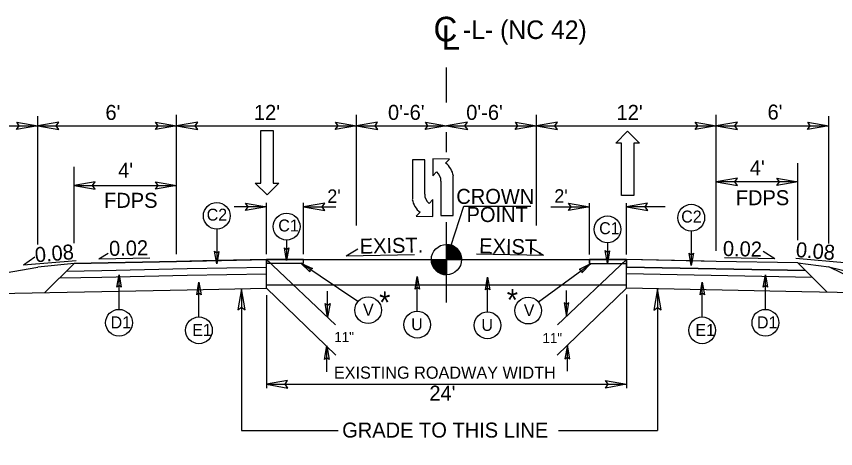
# Model space of a CAD drawing. Extents: x 2111095 to 2115970, y 670428 to 672393.
# Drawn here: x 2112453 to 2112895.7, y 671679.3 to 671912.5 of the extents above; entities that cross this region are included whole.
import ezdxf

# ---------------------------------------------------------------- set-up
doc = ezdxf.new("R2010")
doc.units = 0
for name, color, linetype in [('Old_Level_1', 7, 'Continuous'), ('Old_Level_11', 7, 'Continuous'), ('Old_Level_20', 7, 'Continuous'), ('Old_Level_3', 7, 'Continuous'), ('Prop Lane Arrow CELL', 7, 'Continuous'), ('Prop Leader Line Medium', 7, 'Continuous'), ('Prop Shade Medium', 7, 'Continuous'), ('Typical Grade Point Symbol CELL', 7, 'Continuous'), ('Typical Hinge Slope Arterial CELL', 7, 'Continuous'), ('Typical Pavement Slope CELL', 7, 'Continuous'), ('Typical Pavement Slope Information CELL', 7, 'Continuous'), ('Typical Shoulder Slope CELL', 7, 'Continuous'), ('Typical Shoulder Slope Information CELL', 7, 'Continuous'), ('Typical Terminator CELL', 7, 'Continuous'), ('Typical Text Centerline CELL', 7, 'Continuous'), ('Typical Text General CELL', 7, 'Continuous'), ('Typical Text Grade Point CELL', 7, 'Continuous')]:
    doc.layers.add(name, color=color, linetype=linetype)

msp = doc.modelspace()

# ---------------------------------------------------------------- linework, layer by layer
at = {"layer": 'Old_Level_1'}
for p, q in [((2112588.21, 671781.28), (2112685.41, 671781.28)), ((2112685.41, 671781.28), (2112782.74, 671781.28)), ((2112831.18, 671780.32), (2112782.74, 671781.28)), ((2112588.21, 671765.83), (2112588.21, 671779.34)), ((2112588.21, 671779.34), (2112608.21, 671779.34)), ((2112782.74, 671765.83), (2112782.74, 671779.13)), ((2112891.98, 671777.43), (2113100.62, 671725.29)), ((2113088.33, 671679.28), (2112891.98, 671777.43)), ((2112588.21, 671767.7), (2112685.41, 671767.7)), ((2112685.41, 671767.7), (2112782.58, 671767.7))]:
    msp.add_line(p, q, dxfattribs=at)
at = {"layer": 'Old_Level_11'}
for p, q in [((2112561.29, 671797.66), (2112561.29, 671779.01)), ((2112817.67, 671796.65), (2112817.67, 671777.99)), ((2112599.05, 671791.83), (2112599.05, 671780.85)), ((2112772.42, 671790.37), (2112772.42, 671779.38)), ((2112588.21, 671781.28), (2112625.48, 671745.98)), ((2112782.74, 671781.28), (2112745.47, 671745.98)), ((2112637.57, 671758.66), (2112606.71, 671779.25)), ((2112735.07, 671758.44), (2112763.2, 671778.98)), ((2112508.49, 671754.39), (2112508.49, 671773.08)), ((2112669.61, 671753.38), (2112669.61, 671772.07)), ((2112857.71, 671754.39), (2112857.71, 671773.08)), ((2112551.68, 671750.31), (2112551.68, 671769)), ((2112707.56, 671753), (2112707.56, 671771.69)), ((2112823.57, 671750.31), (2112823.57, 671769)), ((2112588.21, 671765.83), (2112625.7, 671729.73)), ((2112621.2, 671750.11), (2112621.2, 671764.16)), ((2112782.74, 671765.83), (2112745.26, 671729.73)), ((2112750.21, 671750.49), (2112750.21, 671764.54)), ((2112620.71, 671720.7), (2112620.71, 671734.75)), ((2112750.71, 671721.08), (2112750.71, 671735.13))]:
    msp.add_line(p, q, dxfattribs=at)
for points in [[(2112562.44, 671785.69), (2112561.29, 671779.01), (2112560.1, 671785.73), (2112561.29, 671784.88)], [(2112600.2, 671787.53), (2112599.05, 671780.85), (2112597.86, 671787.57), (2112599.05, 671786.72)], [(2112773.57, 671786.07), (2112772.42, 671779.38), (2112771.23, 671786.11), (2112772.42, 671785.25)], [(2112818.82, 671784.68), (2112817.67, 671777.99), (2112816.49, 671784.71), (2112817.67, 671783.86)], [(2112611.63, 671774.58), (2112606.71, 671779.25), (2112612.96, 671776.51), (2112611.59, 671775.99)], [(2112758.48, 671774.11), (2112763.2, 671778.98), (2112757.07, 671775.98), (2112758.46, 671775.52)], [(2112507.34, 671766.39), (2112508.49, 671773.08), (2112509.68, 671766.35), (2112508.49, 671767.21)], [(2112668.46, 671765.38), (2112669.61, 671772.07), (2112670.8, 671765.34), (2112669.61, 671766.2)], [(2112856.56, 671766.39), (2112857.71, 671773.08), (2112858.9, 671766.35), (2112857.71, 671767.21)], [(2112550.52, 671762.31), (2112551.68, 671769), (2112552.86, 671762.28), (2112551.68, 671763.13)], [(2112706.41, 671765.01), (2112707.56, 671771.69), (2112708.75, 671764.97), (2112707.56, 671765.83)], [(2112822.42, 671762.31), (2112823.57, 671769), (2112824.76, 671762.28), (2112823.57, 671763.13)], [(2112622.48, 671757.53), (2112621.2, 671750.11), (2112619.88, 671757.58), (2112621.2, 671756.63)], [(2112748.94, 671757.92), (2112750.21, 671750.49), (2112751.54, 671757.96), (2112750.21, 671757.01)], [(2112619.43, 671727.32), (2112620.71, 671734.75), (2112622.03, 671727.28), (2112620.71, 671728.23)], [(2112751.98, 671727.7), (2112750.71, 671735.13), (2112749.39, 671727.66), (2112750.71, 671728.61)]]:
    msp.add_lwpolyline(points, close=True, dxfattribs=at)
for centre in [(2112561.29, 671804.88), (2112817.67, 671803.86), (2112599.05, 671799.05), (2112772.42, 671797.58), (2112643.06, 671753.98), (2112729.58, 671753.75), (2112508.49, 671747.17), (2112857.71, 671747.17), (2112551.68, 671743.09), (2112669.61, 671746.16), (2112707.56, 671745.79), (2112823.57, 671743.09)]:
    msp.add_circle(centre, 7.22, dxfattribs=at)
at = {"layer": 'Old_Level_3'}
for p, q in [((2112574.64, 671688.99), (2112626.87, 671688.99)), ((2112745.97, 671688.99), (2112799.41, 671688.99))]:
    msp.add_line(p, q, dxfattribs=at)
at = {"layer": 'Prop Lane Arrow CELL'}
for p, q in [((2112585.15, 671822.53), (2112585.15, 671850.88)), ((2112585.15, 671850.88), (2112591.83, 671850.88)), ((2112591.83, 671850.88), (2112591.83, 671822.53)), ((2112776.94, 671844.11), (2112783.22, 671850.48)), ((2112783.22, 671850.48), (2112789.7, 671844.11)), ((2112779.98, 671844.11), (2112776.94, 671844.11)), ((2112779.98, 671815.76), (2112779.98, 671844.11)), ((2112789.7, 671844.11), (2112786.66, 671844.11)), ((2112786.66, 671844.11), (2112786.66, 671815.76)), ((2112666.98, 671835.14), (2112666.98, 671813.78)), ((2112673.67, 671835.14), (2112666.98, 671835.14)), ((2112673.67, 671816.62), (2112673.67, 671835.14)), ((2112678.06, 671835.58), (2112677.96, 671826.46)), ((2112686.97, 671835.47), (2112678.06, 671835.58)), ((2112684.85, 671833.35), (2112686.97, 671835.47)), ((2112677.96, 671826.46), (2112680.09, 671828.59)), ((2112689.1, 671805), (2112689.1, 671826.36)), ((2112588.59, 671816.15), (2112582.11, 671822.53)), ((2112582.11, 671822.53), (2112585.15, 671822.53)), ((2112594.87, 671822.53), (2112588.59, 671816.15)), ((2112591.83, 671822.53), (2112594.87, 671822.53)), ((2112682.42, 671823.53), (2112682.42, 671805)), ((2112678.12, 671813.68), (2112676, 671811.55)), ((2112678.02, 671804.57), (2112678.12, 671813.68)), ((2112786.66, 671815.76), (2112779.98, 671815.76)), ((2112671.24, 671806.79), (2112669.11, 671804.67)), ((2112669.11, 671804.67), (2112678.02, 671804.57)), ((2112682.42, 671805), (2112689.1, 671805))]:
    msp.add_line(p, q, dxfattribs=at)
for centre, radius, start, end in [((2112678.62, 671824.76), 10.64, 8.6761, 53.9878), ((2112675.82, 671823.55), 6.63, 360, 49.6582), ((2112680.26, 671816.59), 6.63, 180, 229.6582), ((2112677.47, 671815.38), 10.64, 188.6761, 233.9878)]:
    msp.add_arc(centre, radius, start, end, dxfattribs=at)
at = {"layer": 'Prop Leader Line Medium'}
for p, q in [((2112685.41, 671865.97), (2112685.41, 671884.94)), ((2112464.58, 671789.41), (2112464.58, 671858.67)), ((2112539.61, 671784.23), (2112539.61, 671859.32)), ((2112636.81, 671799.7), (2112636.81, 671859.32)), ((2112734.01, 671799.7), (2112734.01, 671859.32)), ((2112831.18, 671786.02), (2112831.18, 671859.32)), ((2112891.98, 671789.98), (2112891.98, 671858.68)), ((2112377.61, 671853.48), (2112464.58, 671853.48)), ((2112464.58, 671853.48), (2112539.61, 671853.48)), ((2112539.61, 671853.48), (2112636.81, 671853.48)), ((2112636.81, 671853.48), (2112734.01, 671853.48)), ((2112734.01, 671853.48), (2112831.21, 671853.48)), ((2112831.21, 671853.48), (2112891.98, 671853.48)), ((2112685.41, 671839.26), (2112685.41, 671850)), ((2112484.23, 671790.14), (2112484.23, 671831.32)), ((2112875.32, 671791.75), (2112875.32, 671833.27)), ((2112484.23, 671821.28), (2112539.61, 671821.28)), ((2112875.32, 671823.22), (2112831.18, 671823.22)), ((2112588.21, 671784.23), (2112588.21, 671811.82)), ((2112608.21, 671784.23), (2112608.21, 671811.82)), ((2112762.7, 671784.03), (2112762.7, 671811.75)), ((2112782.7, 671784.03), (2112782.7, 671811.75)), ((2112588.21, 671809.79), (2112570.65, 671809.79)), ((2112608.21, 671809.79), (2112625.66, 671809.79)), ((2112741.85, 671809.79), (2112762.7, 671809.79)), ((2112803.64, 671809.79), (2112782.7, 671809.79)), ((2112685.41, 671758.19), (2112685.41, 671801.4)), ((2112574.64, 671765.55), (2112574.64, 671688.99)), ((2112799.41, 671765.49), (2112799.41, 671688.99)), ((2112588.21, 671762.01), (2112588.21, 671711.93)), ((2112782.74, 671762.42), (2112782.74, 671711.93)), ((2112588.21, 671713.98), (2112782.74, 671713.98))]:
    msp.add_line(p, q, dxfattribs=at)
at = {"layer": 'Prop Shade Medium'}
for p, q in [((2112560.98, 671780.73), (2112539.61, 671780.31)), ((2112561.29, 671779.01), (2112560.98, 671780.73)), ((2112561.59, 671780.75), (2112561.29, 671779.01)), ((2112588.21, 671781.28), (2112561.59, 671780.75)), ((2112588.21, 671777.23), (2112588.21, 671781.28)), ((2112588.21, 671781.28), (2112588.21, 671781.28)), ((2112588.22, 671781.28), (2112588.21, 671781.28)), ((2112588.21, 671781.28), (2112588.21, 671779.34)), ((2112608.21, 671781.28), (2112588.22, 671781.28)), ((2112588.22, 671781.28), (2112590.26, 671779.34)), ((2112590.26, 671779.34), (2112588.22, 671781.28)), ((2112608.21, 671779.34), (2112608.21, 671781.28)), ((2112772.09, 671781.28), (2112762.7, 671781.28)), ((2112762.7, 671781.28), (2112762.7, 671779.13)), ((2112772.42, 671779.38), (2112772.09, 671781.28)), ((2112772.75, 671781.28), (2112772.42, 671779.38)), ((2112782.74, 671781.28), (2112772.75, 671781.28)), ((2112780.48, 671779.13), (2112782.74, 671781.28)), ((2112782.74, 671781.28), (2112780.48, 671779.13)), ((2112817.21, 671780.59), (2112782.74, 671781.28)), ((2112782.74, 671781.28), (2112782.74, 671777.23)), ((2112782.74, 671779.13), (2112782.74, 671781.28)), ((2112817.67, 671777.99), (2112817.21, 671780.59)), ((2112484.23, 671779.2), (2112480.09, 671775.06)), ((2112539.61, 671780.31), (2112484.23, 671779.2)), ((2112499.18, 671775.45), (2112545.27, 671776.37)), ((2112545.27, 671776.37), (2112588.21, 671777.23)), ((2112588.21, 671779.34), (2112590.26, 671779.34)), ((2112590.26, 671779.34), (2112608.21, 671779.34)), ((2112762.7, 671779.13), (2112780.48, 671779.13)), ((2112780.48, 671779.13), (2112782.74, 671779.13)), ((2112782.74, 671777.23), (2112879.45, 671775.31)), ((2112818.12, 671780.58), (2112817.67, 671777.99)), ((2112831.18, 671780.32), (2112818.12, 671780.58)), ((2112875.32, 671779.43), (2112831.18, 671780.32)), ((2112879.45, 671775.31), (2112875.32, 671779.43)), ((2112480.09, 671775.06), (2112499.18, 671775.45))]:
    msp.add_line(p, q, dxfattribs=at)
msp.add_lwpolyline([(2112588.21, 671781.28), (2112588.21, 671781.28)], dxfattribs=at)
at = {"layer": 'Typical Grade Point Symbol CELL'}
for p, q in [((2112685.41, 671781.28), (2112685.41, 671789.43)), ((2112677.25, 671781.28), (2112685.41, 671781.28)), ((2112685.39, 671773.12), (2112685.41, 671781.28)), ((2112685.41, 671781.28), (2112685.39, 671773.12)), ((2112693.57, 671781.28), (2112685.41, 671781.28))]:
    msp.add_line(p, q, dxfattribs=at)
for points in [[(2112685.48, 671789.43), (2112685.48, 671789.43), (2112685.48, 671781.28)], [(2112685.65, 671789.43), (2112685.65, 671781.28)], [(2112685.81, 671789.42), (2112685.81, 671781.28)], [(2112685.97, 671789.42), (2112685.97, 671781.28)], [(2112686.14, 671789.4), (2112686.14, 671781.28)], [(2112686.3, 671789.38), (2112686.3, 671781.28)], [(2112686.46, 671789.36), (2112686.46, 671781.28)], [(2112686.63, 671789.34), (2112686.63, 671781.28)], [(2112686.79, 671789.33), (2112686.79, 671781.28)], [(2112686.95, 671789.29), (2112686.95, 671781.28)], [(2112687.12, 671789.25), (2112687.12, 671781.28)], [(2112687.28, 671789.22), (2112687.28, 671781.28)], [(2112687.44, 671789.18), (2112687.44, 671781.28)], [(2112687.6, 671789.13), (2112687.6, 671781.28)], [(2112687.77, 671789.09), (2112687.77, 671781.28)], [(2112687.93, 671789.04), (2112687.93, 671781.28)], [(2112688.09, 671788.98), (2112688.09, 671781.28)], [(2112688.26, 671788.93), (2112688.26, 671781.28)], [(2112688.42, 671788.85), (2112688.42, 671781.28)], [(2112688.58, 671788.78), (2112688.58, 671781.28)], [(2112688.75, 671788.71), (2112688.75, 671781.28)], [(2112688.91, 671788.64), (2112688.91, 671781.28)], [(2112689.07, 671788.56), (2112689.07, 671781.28)], [(2112689.24, 671788.47), (2112689.24, 671781.28)], [(2112689.4, 671788.38), (2112689.4, 671781.28)], [(2112689.56, 671788.29), (2112689.56, 671781.28)], [(2112689.73, 671788.2), (2112689.73, 671781.28)], [(2112689.89, 671788.09), (2112689.89, 671781.28)], [(2112690.05, 671787.98), (2112690.05, 671781.28)], [(2112690.22, 671787.86), (2112690.22, 671781.28)], [(2112690.38, 671787.75), (2112690.38, 671781.28)], [(2112690.54, 671787.62), (2112690.54, 671781.28)], [(2112690.71, 671787.48), (2112690.71, 671781.28)], [(2112690.87, 671787.33), (2112690.87, 671781.28)], [(2112691.03, 671787.19), (2112691.03, 671781.28)], [(2112691.19, 671787.02), (2112691.19, 671781.28)], [(2112691.36, 671786.86), (2112691.36, 671781.28)], [(2112691.52, 671786.68), (2112691.52, 671781.28)], [(2112691.68, 671786.48), (2112691.68, 671781.28)], [(2112691.85, 671786.28), (2112691.85, 671781.28)], [(2112692.01, 671786.06), (2112692.01, 671781.28)], [(2112692.17, 671785.83), (2112692.17, 671781.28)], [(2112692.34, 671785.57), (2112692.34, 671781.28)], [(2112692.5, 671785.3), (2112692.5, 671781.28)], [(2112692.66, 671785.01), (2112692.66, 671781.28)], [(2112677.29, 671781.28), (2112677.29, 671780.39)], [(2112677.45, 671781.28), (2112677.45, 671779.43)], [(2112677.62, 671781.28), (2112677.62, 671778.85)], [(2112677.78, 671781.28), (2112677.78, 671778.36)], [(2112677.94, 671781.28), (2112677.94, 671777.98)], [(2112678.11, 671781.28), (2112678.11, 671777.63)], [(2112678.27, 671781.28), (2112678.27, 671777.33)], [(2112678.43, 671781.28), (2112678.43, 671777.04)], [(2112678.6, 671781.28), (2112678.6, 671776.78)], [(2112678.76, 671781.28), (2112678.76, 671776.55)], [(2112678.92, 671781.28), (2112678.92, 671776.33)], [(2112679.08, 671781.28), (2112679.08, 671776.13)], [(2112679.25, 671781.28), (2112679.25, 671775.93)], [(2112679.41, 671781.28), (2112679.41, 671775.75)], [(2112679.57, 671781.28), (2112679.57, 671775.57)], [(2112679.74, 671781.28), (2112679.74, 671775.4)], [(2112679.9, 671781.28), (2112679.9, 671775.26)], [(2112680.06, 671781.28), (2112680.06, 671775.11)], [(2112680.23, 671781.28), (2112680.23, 671774.97)], [(2112680.39, 671781.28), (2112680.39, 671774.84)], [(2112680.55, 671781.28), (2112680.55, 671774.71)], [(2112680.72, 671781.28), (2112680.72, 671774.61)], [(2112680.88, 671781.28), (2112680.88, 671774.5)], [(2112681.04, 671781.28), (2112681.04, 671774.39)], [(2112681.21, 671781.28), (2112681.21, 671774.28)], [(2112681.37, 671781.28), (2112681.37, 671774.19)], [(2112681.53, 671781.28), (2112681.53, 671774.1)], [(2112681.7, 671781.28), (2112681.7, 671774.01)], [(2112681.86, 671781.28), (2112681.86, 671773.94)], [(2112682.02, 671781.28), (2112682.02, 671773.86)], [(2112682.19, 671781.28), (2112682.19, 671773.79)], [(2112682.35, 671781.28), (2112682.35, 671773.72)], [(2112682.51, 671781.28), (2112682.51, 671773.65)], [(2112682.67, 671781.28), (2112682.67, 671773.59)], [(2112682.84, 671781.28), (2112682.84, 671773.54)], [(2112683, 671781.28), (2112683, 671773.48)], [(2112683.16, 671781.28), (2112683.16, 671773.45)], [(2112683.33, 671781.28), (2112683.33, 671773.39)], [(2112683.49, 671781.28), (2112683.49, 671773.36)], [(2112683.65, 671781.28), (2112683.65, 671773.32)], [(2112683.82, 671781.28), (2112683.82, 671773.28)], [(2112683.98, 671781.28), (2112683.98, 671773.25)], [(2112684.14, 671781.28), (2112684.14, 671773.23)], [(2112684.31, 671781.28), (2112684.31, 671773.19)], [(2112684.47, 671781.28), (2112684.47, 671773.17)], [(2112684.63, 671781.28), (2112684.63, 671773.16)], [(2112684.8, 671781.28), (2112684.8, 671773.14)], [(2112684.96, 671781.28), (2112684.96, 671773.14)], [(2112685.12, 671781.28), (2112685.12, 671773.12)], [(2112685.29, 671781.28), (2112685.29, 671773.12), (2112685.29, 671773.12)], [(2112692.83, 671784.67), (2112692.83, 671781.28)], [(2112692.99, 671784.29), (2112692.99, 671781.28)], [(2112693.15, 671783.83), (2112693.15, 671781.28)], [(2112693.32, 671783.27), (2112693.32, 671781.28)], [(2112693.48, 671782.44), (2112693.48, 671781.28)]]:
    msp.add_lwpolyline(points, dxfattribs=at)
msp.add_circle((2112685.4, 671781.28), 8.16, dxfattribs=at)
for start, end in [(359.9905, 89.9905), (179.9905, 269.9905)]:
    msp.add_arc((2112685.4, 671781.28), 8.16, start, end, dxfattribs=at)
at = {"layer": 'Typical Hinge Slope Arterial CELL'}
msp.add_line((2112377.61, 671761.61), (2112464.58, 671777.25), dxfattribs=at)
at = {"layer": 'Typical Pavement Slope CELL'}
for p, q in [((2112539.61, 671780.31), (2112588.21, 671781.28)), ((2112608.21, 671779.34), (2112608.21, 671781.28)), ((2112762.7, 671779.13), (2112762.7, 671781.28)), ((2112484.23, 671779.2), (2112468.46, 671763.43)), ((2112484.23, 671779.2), (2112539.61, 671780.31)), ((2112499.18, 671775.45), (2112545.27, 671776.37)), ((2112545.27, 671776.37), (2112588.21, 671777.23)), ((2112762.7, 671779.13), (2112782.74, 671779.13)), ((2112879.45, 671775.31), (2112782.74, 671777.23)), ((2112875.32, 671779.43), (2112831.18, 671780.32)), ((2112891.1, 671763.66), (2112875.32, 671779.43)), ((2112476.43, 671771.4), (2112499.18, 671771.86)), ((2112480.09, 671775.06), (2112499.18, 671775.45)), ((2112499.18, 671771.86), (2112545.27, 671772.78)), ((2112545.27, 671772.78), (2112588.21, 671773.64)), ((2112883.12, 671771.64), (2112782.74, 671773.64)), ((2112377.61, 671761.61), (2112499.18, 671764.04)), ((2112499.18, 671764.04), (2112545.27, 671764.97)), ((2112545.27, 671764.97), (2112588.21, 671765.83)), ((2112877.47, 671763.93), (2112782.74, 671765.83)), ((2112951.96, 671762.44), (2112877.47, 671763.93))]:
    msp.add_line(p, q, dxfattribs=at)
at = {"layer": 'Typical Pavement Slope Information CELL'}
for p, q in [((2112631.2, 671783.26), (2112637.54, 671787.09)), ((2112737.78, 671783.4), (2112731.44, 671787.23)), ((2112862.79, 671781.7), (2112856.45, 671785.54)), ((2112456.96, 671778.44), (2112463.04, 671782.67)), ((2112456.96, 671778.44), (2112485.38, 671780.83)), ((2112497.64, 671781.74), (2112502.62, 671784.75)), ((2112497.64, 671781.74), (2112525.1, 671782.29)), ((2112631.2, 671783.26), (2112668.08, 671784)), ((2112737.78, 671783.4), (2112701.71, 671784.12)), ((2112862.79, 671781.7), (2112835.66, 671782.24)), ((2112902.52, 671779.39), (2112874.1, 671781.78))]:
    msp.add_line(p, q, dxfattribs=at)
at = {"layer": 'Typical Shoulder Slope CELL'}
for p, q in [((2112484.23, 671779.2), (2112464.58, 671777.25)), ((2112875.32, 671779.43), (2112891.98, 671777.43))]:
    msp.add_line(p, q, dxfattribs=at)
at = {"layer": 'Typical Terminator CELL'}
for points in [[(2112453.19, 671855.44), (2112464.58, 671853.48), (2112453.13, 671851.45), (2112454.59, 671853.48)], [(2112475.97, 671855.44), (2112464.58, 671853.48), (2112476.04, 671851.45), (2112474.58, 671853.48)], [(2112528.22, 671855.44), (2112539.61, 671853.48), (2112528.16, 671851.45), (2112529.62, 671853.48)], [(2112551, 671855.44), (2112539.61, 671853.48), (2112551.07, 671851.45), (2112549.61, 671853.48)], [(2112625.42, 671855.44), (2112636.81, 671853.48), (2112625.36, 671851.45), (2112626.82, 671853.48)], [(2112648.2, 671855.44), (2112636.81, 671853.48), (2112648.27, 671851.45), (2112646.81, 671853.48)], [(2112674.02, 671855.44), (2112685.41, 671853.48), (2112673.96, 671851.45), (2112675.42, 671853.48)], [(2112696.8, 671855.44), (2112685.41, 671853.48), (2112696.87, 671851.45), (2112695.41, 671853.48)], [(2112722.62, 671855.44), (2112734.01, 671853.48), (2112722.56, 671851.45), (2112724.02, 671853.48)], [(2112745.4, 671855.44), (2112734.01, 671853.48), (2112745.47, 671851.45), (2112744.01, 671853.48)], [(2112819.82, 671855.44), (2112831.21, 671853.48), (2112819.76, 671851.45), (2112821.22, 671853.48)], [(2112842.6, 671855.44), (2112831.21, 671853.48), (2112842.67, 671851.45), (2112841.21, 671853.48)], [(2112880.59, 671855.44), (2112891.98, 671853.48), (2112880.53, 671851.45), (2112881.98, 671853.48)], [(2112842.57, 671825.18), (2112831.18, 671823.22), (2112842.63, 671821.2), (2112841.18, 671823.22)], [(2112863.93, 671825.18), (2112875.32, 671823.22), (2112863.87, 671821.2), (2112865.32, 671823.22)], [(2112495.61, 671823.24), (2112484.23, 671821.28), (2112495.68, 671819.25), (2112494.22, 671821.28)], [(2112528.22, 671823.24), (2112539.61, 671821.28), (2112528.16, 671819.25), (2112529.62, 671821.28)], [(2112576.83, 671811.75), (2112588.21, 671809.79), (2112576.76, 671807.76), (2112578.22, 671809.79)], [(2112619.6, 671811.75), (2112608.21, 671809.79), (2112619.67, 671807.76), (2112618.21, 671809.79)], [(2112751.32, 671811.75), (2112762.7, 671809.79), (2112751.25, 671807.76), (2112752.71, 671809.79)], [(2112794.09, 671811.75), (2112782.7, 671809.79), (2112794.16, 671807.76), (2112792.7, 671809.79)], [(2112576.6, 671754.16), (2112574.64, 671765.55), (2112572.61, 671754.1), (2112574.64, 671755.56)], [(2112801.37, 671754.1), (2112799.41, 671765.49), (2112797.38, 671754.04), (2112799.41, 671755.5)], [(2112599.6, 671715.94), (2112588.21, 671713.98), (2112599.67, 671711.96), (2112598.21, 671713.98)], [(2112771.35, 671715.94), (2112782.74, 671713.98), (2112771.29, 671711.96), (2112772.74, 671713.98)]]:
    msp.add_lwpolyline(points, close=True, dxfattribs=at)
at = {"layer": 'Typical Text Grade Point CELL'}
for p, q in [((2112685.41, 671781.28), (2112694.83, 671810.03)), ((2112694.83, 671810.03), (2112730.92, 671810.03))]:
    msp.add_line(p, q, dxfattribs=at)

# ---------------------------------------------------------------- texts
at = {"layer": 'Old_Level_11'}
for p in [(2112624.81, 671736.8), (2112737.28, 671736.2)]:
    msp.add_text('11"', height=5.4, dxfattribs=at).set_placement(p)
at = {"layer": 'Old_Level_20'}
for s, height, p in [('C2', 6.461, (2112555.85, 671802.27)), ('C2', 6.461, (2112812.24, 671801.25)), ('C1', 6.461, (2112594.54, 671796.43)), ('C1', 6.461, (2112767.91, 671794.97)), ('V', 6.46, (2112640.32, 671750.97)), ('V', 6.46, (2112727.18, 671750.74)), ('D1', 6.461, (2112503.96, 671744.16)), ('U', 6.46, (2112666.34, 671743.15)), ('D1', 6.461, (2112853.18, 671744.16)), ('E1', 6.461, (2112548.02, 671740.08)), ('U', 6.46, (2112704.29, 671742.78)), ('E1', 6.461, (2112819.92, 671740.08))]:
    msp.add_text(s, height=height, dxfattribs=at).set_placement(p)
at = {"layer": 'Prop Leader Line Medium'}
for s, height, p in [('-L- (NC 42)', 10, (2112694.33, 671900.29)), ("6'", 8.1, (2112501.15, 671856.62)), ("12'", 8.1, (2112581.37, 671856.64)), ("0'-6'", 8.1, (2112653.8, 671856.64)), ("0'-6'", 8.1, (2112696.08, 671856.64)), ("12'", 8.1, (2112777.31, 671856.64)), ("6'", 8.1, (2112858.88, 671856.81)), ("4'", 8.1, (2112849.31, 671826.81)), ("4'", 8.1, (2112508.01, 671825.39)), ('FDPS', 8.1, (2112500.39, 671809.19)), ("2'", 7.29, (2112621, 671811.82)), ("2'", 7.29, (2112743.65, 671811.91)), ('FDPS', 8.1, (2112841.7, 671810.61)), ('EXISTING ROADWAY WIDTH', 6.561, (2112624.56, 671716.99)), ("24'", 8.1, (2112676.17, 671705.15))]:
    msp.add_text(s, height=height, rotation=360, dxfattribs=at).set_placement(p)
at = {"layer": 'Typical Pavement Slope Information CELL'}
for s, height, rotation, p in [('0.02', 8.1, 1.1457, (2112503.18, 671783.22)), ('EXIST.', 8.1, 1.1457, (2112638.61, 671784.43)), ('EXIST.', 8.1, 358.8543, (2112703.02, 671784.67)), ('0.02', 8.1, 358.8543, (2112834.7, 671783.24)), ('*', 11.67, 358.8561, (2112648.85, 671752.44)), ('*', 11.67, 358.8561, (2112717.81, 671753.77))]:
    msp.add_text(s, height=height, rotation=rotation, dxfattribs=at).set_placement(p)
at = {"layer": 'Typical Shoulder Slope Information CELL'}
for rotation, p in [(4.7615, (2112463.35, 671779.75)), (355.2385, (2112873.94, 671782.7))]:
    msp.add_text('0.08', height=8.1, rotation=rotation, dxfattribs=at).set_placement(p)
at = {"layer": 'Typical Text Centerline CELL'}
for s, rotation, p in [('C', 360, (2112678.41, 671899)), ('L', 359.9469, (2112682.82, 671894.46))]:
    msp.add_text(s, height=13.29, rotation=rotation, dxfattribs=at).set_placement(p)
at = {"layer": 'Typical Text General CELL'}
msp.add_text('GRADE TO THIS LINE', height=8.1, rotation=360, dxfattribs=at).set_placement((2112629.06, 671685.22))
at = {"layer": 'Typical Text Grade Point CELL'}
for s, p in [('CROWN', (2112690.72, 671811.3)), ('POINT', (2112696.25, 671801.54))]:
    msp.add_text(s, height=8.1, rotation=360, dxfattribs=at).set_placement(p)

doc.saveas('drawing.dxf')
